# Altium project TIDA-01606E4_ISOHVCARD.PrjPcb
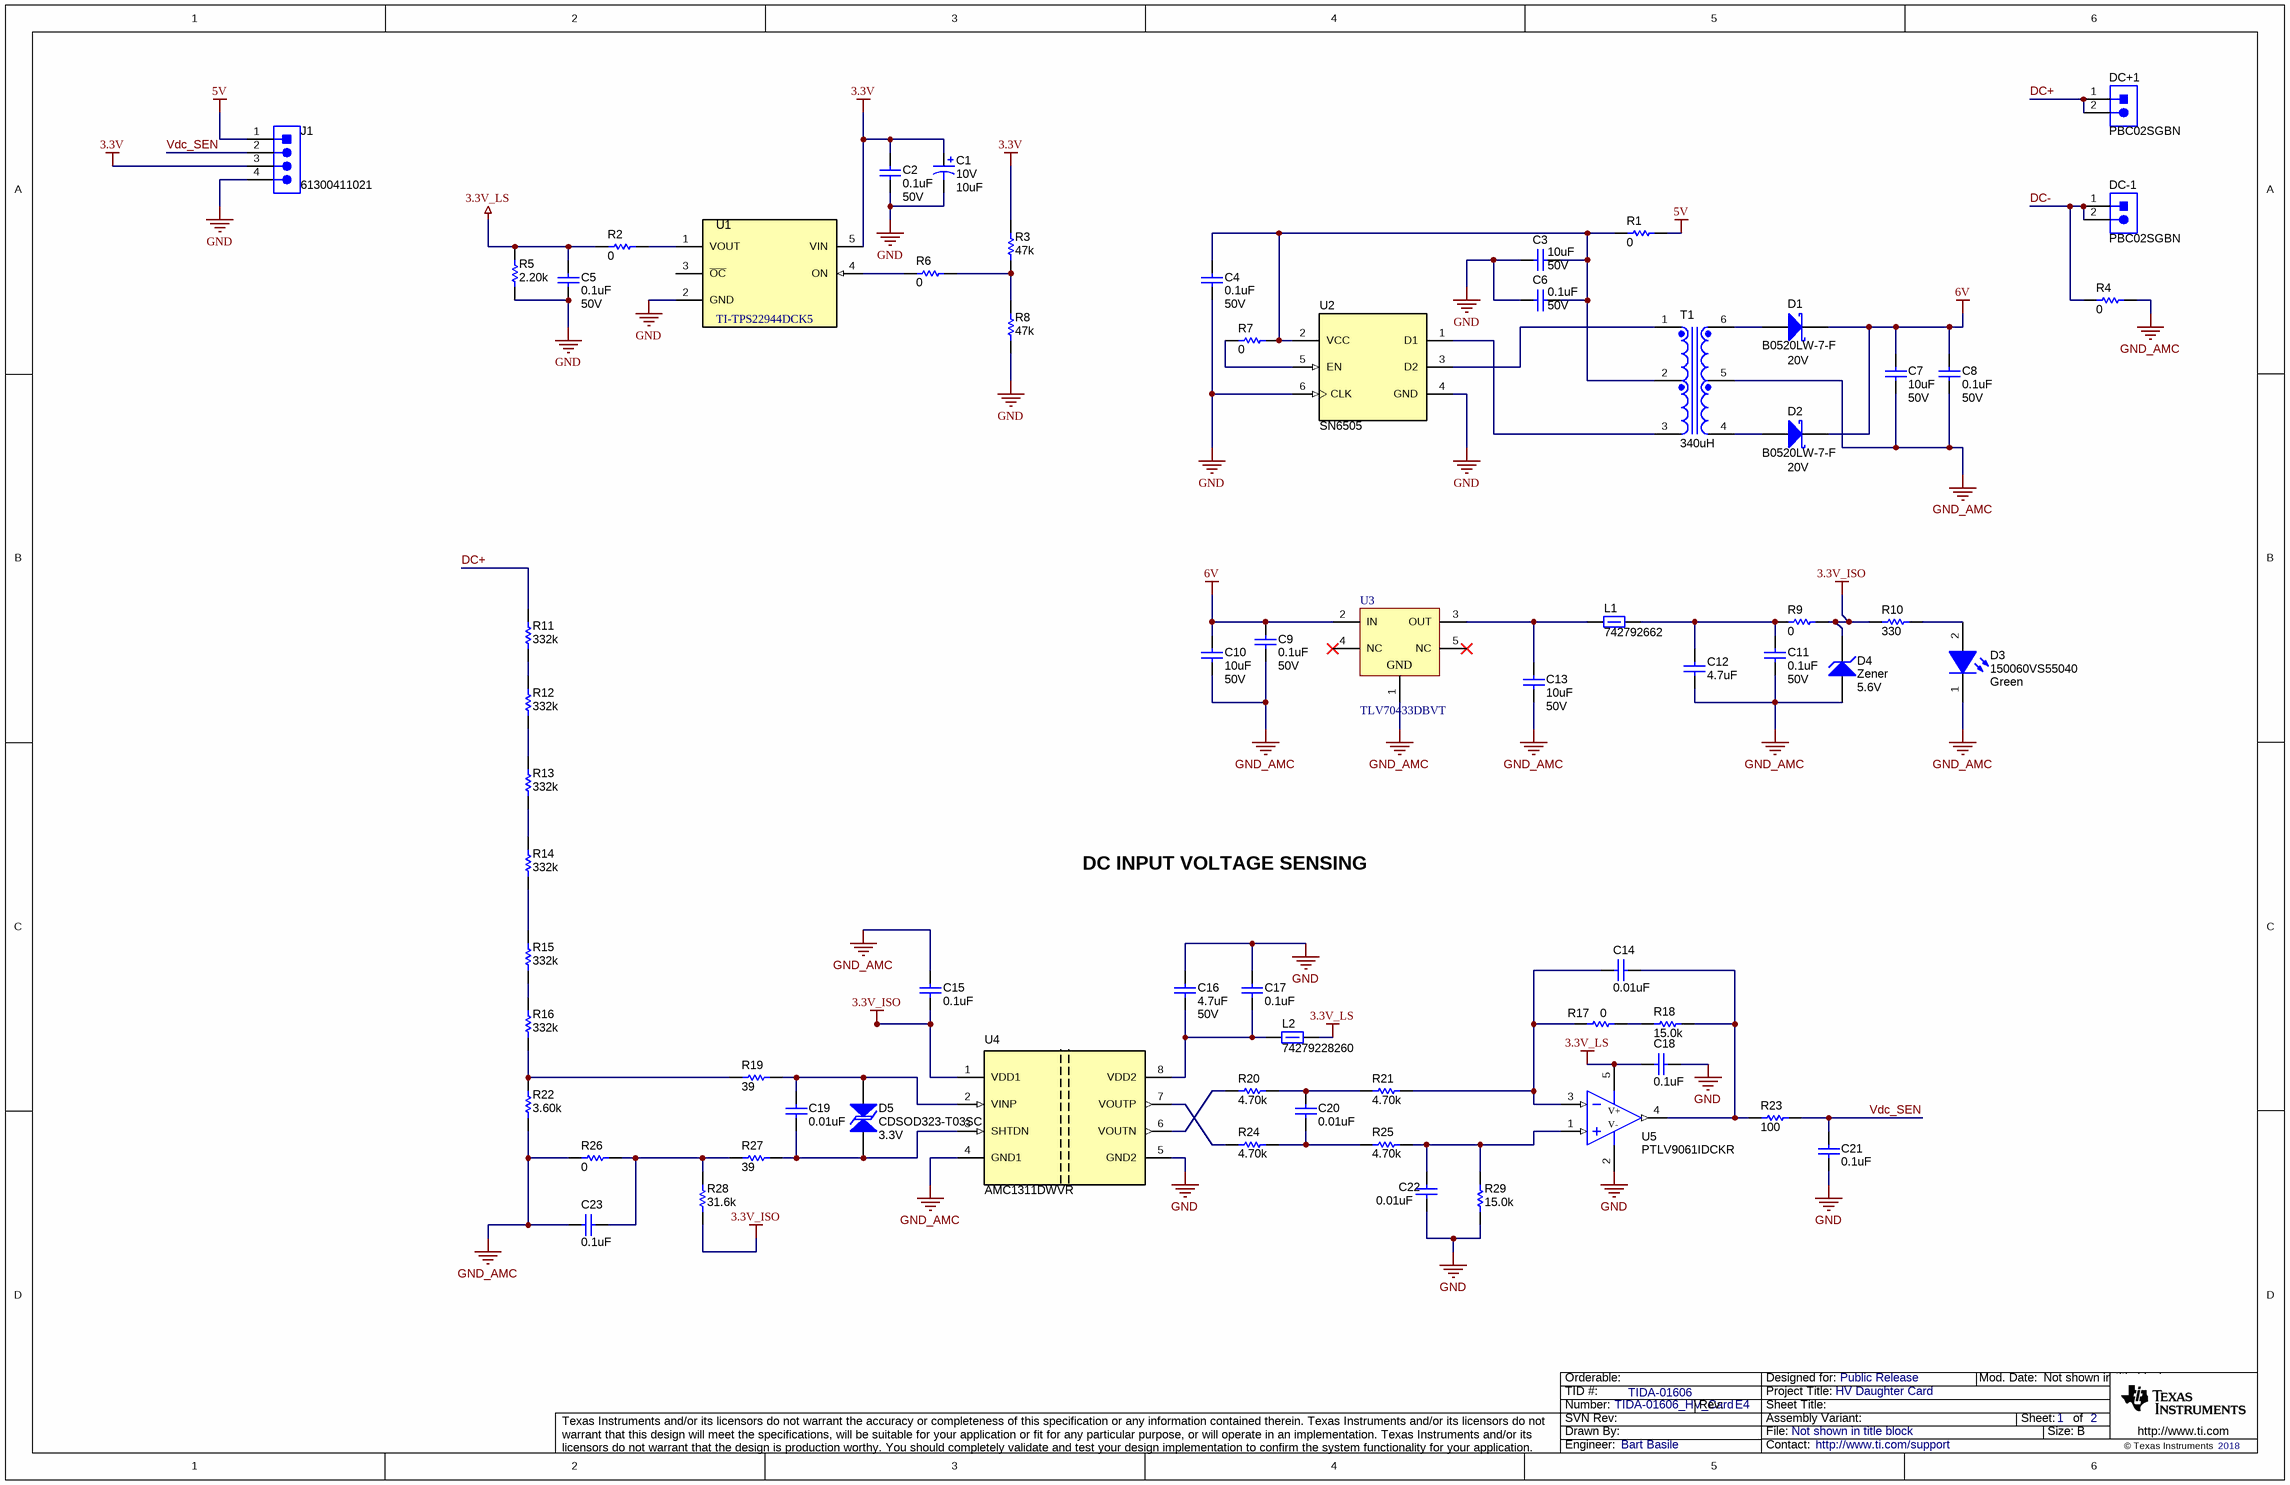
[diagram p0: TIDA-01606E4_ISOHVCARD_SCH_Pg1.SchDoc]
CopyrightYear: 2018; PCB_Layout: Bart Basile; PCB_Rev: E4; PRJ_Customer: Public Release; PRJ_Engineer: Bart Basile; PRJ_Number: TIDA-01606_HV_Card; PRJ_Title: HV Daughter Card; SCH_Rev: E4; TechSupport: http://www.ti.com/support; TID: TIDA-01606
2 sheets, 83 parts. Net scope: global (net labels, ports and power ports of the same name join across sheets).
Board file: TIDA-01606E4_ISOHVCARD_PCB.PcbDoc
Sheets:
  TIDA-01606E4_ISOHVCARD_SCH_Pg1.SchDoc
  TIDA-01606E4_ISOHVCARD_EVM_Hardware_Pg2.SchDoc

## Sheet TIDA-01606E4_ISOHVCARD_SCH_Pg1.SchDoc
size 431 x 279 mm; Date: Not shown in title block; ApprovedBy: Not shown in title block; CheckedBy: Not shown in title block; Author: Not shown in title block; CompanyName: Not shown in title block; Engineer: Not shown in title block; Organization: Not shown in title block; Address1: Not shown in title block; Address2: Not shown in title block; Address3: Not shown in title block; Address4: Not shown in title block; DocumentNumber: 1; Revision: Use project parameter SCH_Rev; SheetNumber: 1; SheetTotal: 2; PageSetup: Record=PageOptions¦CenterHorizontal=True¦CenterVertical=True¦PrintScale=1.00¦XCorrection=1.00¦YCorrection=1.00¦PrintKind=0¦BorderSize=5000000¦LeftOffset=0¦BottomOffset=0¦Orientation=2¦PaperLength=1000¦PaperWidth=1000¦Scale=100¦PaperSource=15¦PrintQuality=600¦MediaType=1¦DitherType=10¦PaperKind=Letter¦PrintScaleMode=1

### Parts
C1  VDC_V: 10V  ValueDisplayed: 10uF  [3216-18]  (hidden comment: TAJA106M010RNJ)
C2  ValueDisplayed: 0.1uF  VDC_V: 50V  [0603]  (hidden comment: 885012206095)
C3  ValueDisplayed: 10uF  VDC_V: 50V  [1210_280]  (hidden comment: C3225X7R1H106M250AC)
C4  ValueDisplayed: 0.1uF  VDC_V: 50V  [0603]  (hidden comment: 885012206095)
C5  ValueDisplayed: 0.1uF  VDC_V: 50V  [0603]  (hidden comment: 885012206095)
C6  ValueDisplayed: 0.1uF  VDC_V: 50V  [0603]  (hidden comment: 885012206095)
C7  ValueDisplayed: 10uF  VDC_V: 50V  [1210_280]  (hidden comment: C3225X7R1H106M250AC)
C8  ValueDisplayed: 0.1uF  VDC_V: 50V  [0603]  (hidden comment: 885012206095)
C9  ValueDisplayed: 0.1uF  VDC_V: 50V  [0603]  (hidden comment: 885012206095)
C10  ValueDisplayed: 10uF  VDC_V: 50V  [1210_280]  (hidden comment: C3225X7R1H106M250AC)
C11  ValueDisplayed: 0.1uF  VDC_V: 50V  [0603]  (hidden comment: 885012206095)
C12  ValueDisplayed: 4.7uF  [0805_HV]  (hidden comment: GRM21BR61H475KE51L)
C13  ValueDisplayed: 10uF  VDC_V: 50V  [1210_280]  (hidden comment: C3225X7R1H106M250AC)
C14  ValueDisplayed: 0.01uF  [0603]  (hidden comment: Capacitor)
C15  ValueDisplayed: 0.1uF  [0603]  (hidden comment: Capacitor)
C16  ValueDisplayed: 4.7uF  VDC_V: 50V  [0805_HV]  (hidden comment: GRM21BR61H475KE51L)
C17  ValueDisplayed: 0.1uF  [0603]  (hidden comment: Capacitor)
C18  ValueDisplayed: 0.1uF  [0603]  (hidden comment: Capacitor)
C19  ValueDisplayed: 0.01uF  [0603]  (hidden comment: Capacitor)
C20  ValueDisplayed: 0.01uF  [0603]  (hidden comment: Capacitor)
C21  ValueDisplayed: 0.1uF  [0603]  (hidden comment: Capacitor)
C22  ValueDisplayed: 0.01uF  [0603]  (hidden comment: Capacitor)
C23  ValueDisplayed: 0.1uF  [0603]  (hidden comment: Capacitor)
D1  B0520LW-7-F  value 20V  [SOD-123]
D2  B0520LW-7-F  value 20V  [SOD-123]
D3  150060VS55040  value Green  [WL-SMCD-0603]
D4  Zener  value 5.6V  [SOD-123]
D5  CDSOD323-T03SC  value 3.3V  [SOD-323-Bi]
DC+1  PBC02SGBN  [Sullins_PxC02SGBN]
DC-1  PBC02SGBN  [Sullins_PxC02SGBN]
J1  61300411021  [Wurth_61300411021]
L1  742792662  [0603]
L2  74279228260  [0603]
R1  ValueDisplayed: 0  [0603]  (hidden comment: ERJ-3GEY0R00V)
R2  ValueDisplayed: 0  [0603]  (hidden comment: ERJ-3GEY0R00V)
R3  ValueDisplayed: 47k  [0603]  (hidden comment: Resistor)
R4  ValueDisplayed: 0  [0603]  (hidden comment: ERJ-3GEY0R00V)
R5  ValueDisplayed: 2.20k  [0603]  (hidden comment: Resistor)
R6  ValueDisplayed: 0  [0402]  (hidden comment: CRCW04020000Z0ED)
R7  ValueDisplayed: 0  [0603]  (hidden comment: ERJ-3GEY0R00V)
R8  ValueDisplayed: 47k  [0603]  (hidden comment: Resistor)
R9  ValueDisplayed: 0  [0603]  (hidden comment: ERJ-3GEY0R00V)
R10  ValueDisplayed: 330  [0603]  (hidden comment: RC0603JR-07330RL)
R11  ValueDisplayed: 332k  [MMU_0102]  (hidden comment: MMU01020C3323FB300)
R12  ValueDisplayed: 332k  [MMU_0102]  (hidden comment: MMU01020C3323FB300)
R13  ValueDisplayed: 332k  [MMU_0102]  (hidden comment: MMU01020C3323FB300)
R14  ValueDisplayed: 332k  [MMU_0102]  (hidden comment: MMU01020C3323FB300)
R15  ValueDisplayed: 332k  [MMU_0102]  (hidden comment: MMU01020C3323FB300)
R16  ValueDisplayed: 332k  [MMU_0102]  (hidden comment: MMU01020C3323FB300)
R17  ValueDisplayed: 0  [0603]  (hidden comment: Resistor)
R18  ValueDisplayed: 15.0k  [0603]  (hidden comment: Resistor)
R19  ValueDisplayed: 39  [0603]  (hidden comment: Resistor)
R20  ValueDisplayed: 4.70k  [0603]  (hidden comment: Resistor)
R21  ValueDisplayed: 4.70k  [0603]  (hidden comment: Resistor)
R22  ValueDisplayed: 3.60k  [MMU_0102]  (hidden comment: MMU01020C3601FB300)
R23  ValueDisplayed: 100  [0603]  (hidden comment: ERJ-3EKF1000V)
R24  ValueDisplayed: 4.70k  [0603]  (hidden comment: Resistor)
R25  ValueDisplayed: 4.70k  [0603]  (hidden comment: Resistor)
R26  ValueDisplayed: 0  [0603]  (hidden comment: ERJ-3GEY0R00V)
R27  ValueDisplayed: 39  [0603]  (hidden comment: Resistor)
R28  ValueDisplayed: 31.6k  [0603]  (hidden comment: Resistor)
R29  ValueDisplayed: 15.0k  [0603]  (hidden comment: Resistor)
T1  ValueDisplayed: 340uH  [Wurth_750313638]  (hidden comment: 750313638)
U1  TI-TPS22944DCK5  [DCK0005A_N]
U2  SN6505  [DBV0006A_N]
U3  TLV70433DBVT  [DBV0005A_N]
U4  AMC1311DWVR  [DWV0008A]
U5  PTLV9061IDCKR  [DCK0005A_N]

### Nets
3.3V: C1.1(+) C2.2 J1.3 R3.2 U1.5(VIN)
3.3V_ISO: C15.2 D4.1(K) R9.2 R10.1 R28.1 U4.1(VDD1)
3.3V_LS: C5.2 C18.1 L2.2 R2.1 R5.1 U5.5(V+)
5V: J1.1 R1.2
6V: C7.1 C8.1 C9.1 C10.2 D1.1(K) D2.1(K) U3.2(IN)
GND: C1.2(-) C2.1 C3.1 C4.1 C5.1 C6.1 C16.1 C17.1 C18.2 C21.2 C22.2 J1.4 R5.2 R8.1 R29.1 U1.2(GND) U2.4(GND) U2.6(CLK) U4.5(GND2) U5.2(V-)
GND_AMC: C7.2 C8.2 C9.2 C10.1 C11.2 C12.1 C13.1 C15.1 C23.1 D3.1(K) D4.2(A) R4.2 R22.1 R26.1 T1.5 U3.1(GND) U4.4(GND1)
DC+: DC+1.1 DC+1.2 R11.2
DC-: DC-1.1 DC-1.2 R4.1
Vdc_SEN: C21.1 J1.2 R23.2
NetC3_2: C3.2 C4.2 C6.2 R1.1 R7.1 T1.2 U2.2(VCC)
NetC11_1: C11.1 C12.2 L1.2 R9.1
NetC13_2: C13.2 L1.1 U3.3(OUT)
NetC14_1: C14.1 R17.1 R21.2 U5.3(-IN)
NetC14_2: C14.2 R18.1 R23.1 U5.4(OUT)
NetC16_2: C16.2 C17.2 L2.1 U4.8(VDD2)
NetC19_1: C19.1 D5.2 R19.2 U4.2(VINP)
NetC19_2: C19.2 D5.1 R27.2 U4.3(SHTDN)
NetC20_1: C20.1 R20.2 R21.1
NetC20_2: C20.2 R24.2 R25.1
NetC22_1: C22.1 R25.2 R29.2 U5.1(+IN)
NetC23_2: C23.2 R26.2 R27.1 R28.2
NetD1_2: D1.2(A) T1.6
NetD2_2: D2.2(A) T1.4
NetD3_2: D3.2(A) R10.2
NetR2_2: R2.2 U1.1(VOUT)
NetR3_1: R3.1 R6.2 R8.2
NetR6_1: R6.1 U1.4(ON)
NetR7_2: R7.2 U2.5(EN)
NetR11_1: R11.1 R12.2
NetR12_1: R12.1 R13.2
NetR13_1: R13.1 R14.2
NetR14_1: R14.1 R15.2
NetR15_1: R15.1 R16.2
NetR16_1: R16.1 R19.1 R22.2
NetR17_2: R17.2 R18.2
NetR20_1: R20.1 U4.6(VOUTN)
NetR24_1: R24.1 U4.7(VOUTP)
NetT1_1: T1.1 U2.3(D2)
NetT1_3: T1.3 U2.1(D1)

Not connected (* = marked no-connect by the designer): U1 3(~{OC}); U3 4(NC)* 5(NC)*

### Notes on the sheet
- DC INPUT VOLTAGE SENSING

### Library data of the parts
C1 = CMP-0011478-2: CAP, TA, 10 uF, 10 V, +/- 20%, 3 ohm, SMD; Manufacturer: AVX; TaMin_C: -55°C; ESR_ohm: 3; Polarized: Y; SizeAreaWB_mm2: 10.92; Value1: 3 ohm; U/M: EA; Value: 10uF; TaMax_C: 125°C; SizeZ_mm: 1.8; SizeX_mm: 3.2; SizeY_mm: 1.6; SizeArea_mm2: 5.12; CompType: Capacitor; Cap_F: 10µF; AEC Category: Q200
C2 C4-C6 C8 C9 C11 = CMP-0006837-4: CAP, CERM, 0.1 uF, 50 V, +/- 10%, X7R, 0603; Manufacturer: Wurth Elektronik; Polarized: N; Value: 0.1uF; U/M: EA; Cap_F: 100nF; Value1: Unknown; TaMin_C: -55°C; TaMax_C: 125°C; AEC Category: Q200; SizeArea_mm2: 1.28; SizeAreaWB_mm2: 4.68; SizeX_mm: 1.6; SizeY_mm: 0.8; SizeZ_mm: 1
C3 C7 C10 C13 = CMP-0009120-1: CAP, CERM, 10 uF, 50 V, +/- 20%, X7R, 1210; Manufacturer: TDK; Polarized: N; Value: 10uF; U/M: EA; Cap_F: 10µF; Value1: Unknown; TaMin_C: -55°C; TaMax_C: 125°C; Cap_Case: 1210; AEC Category: Q200; SizeArea_mm2: 8; SizeAreaWB_mm2: 14.7; SizeX_mm: 3.2; SizeY_mm: 2.5; SizeZ_mm: 2.8
C12 = CMP-0008309-2: CAP, CERM, 4.7 uF, 50 V, +/- 10%, X5R, 0805; Manufacturer: MuRata; Polarized: N; CompType: Capacitor; Value: 4.7uF; U/M: EA; Cap_F: 4.7µF; Value1: Unknown; VDC_V: 50V; TaMin_C: -55°C; TaMax_C: 85°C; Cap_Case: 0805; AEC Category: Q200; SizeArea_mm2: 2.5; SizeAreaWB_mm2: 6.75; SizeX_mm: 2; SizeY_mm: 1.25; SizeZ_mm: 1.45
C14 C19 C20 C22 = CMP-0006828-4: CAP, CERM, 0.01 uF, 16 V, +/- 10%, X7R, 0603; PartNumber: 885012206040; Manufacturer: Wurth Elektronik; Polarized: N; Value: 0.01uF; U/M: EA; Cap_F: 10nF; Value1: Unknown; VDC_V: 16V; TaMin_C: -55°C; TaMax_C: 125°C; AEC Category: Q200; SizeArea_mm2: 1.28; SizeAreaWB_mm2: 4.68; SizeX_mm: 1.6; SizeY_mm: 0.8; SizeZ_mm: 1
C15 C17 C18 C21 C23 = CMP-0007434-4: CAP, CERM, 0.1 uF, 50 V, +/- 10%, X7R, 0603; PartNumber: GRM188R71H104KA93D; Manufacturer: MuRata; Polarized: N; Value: 0.1uF; U/M: EA; Cap_F: 100nF; Value1: Unknown; VDC_V: 50V; TaMin_C: -55°C; TaMax_C: 125°C; AEC Category: Q200; SizeArea_mm2: 1.28; SizeAreaWB_mm2: 4.68; SizeX_mm: 1.6; SizeY_mm: 0.8; SizeZ_mm: 1
C16 = CMP-0008309-2: CAP, CERM, 4.7 uF, 50 V, +/- 10%, X5R, 0805; Manufacturer: MuRata; Polarized: N; Value: 4.7uF; U/M: EA; Cap_F: 4.7µF; Value1: Unknown; TaMin_C: -55°C; TaMax_C: 85°C; Cap_Case: 0805; AEC Category: Q200; SizeArea_mm2: 2.5; SizeAreaWB_mm2: 6.75; SizeX_mm: 2; SizeY_mm: 1.25; SizeZ_mm: 1.45
D1 D2 = CMP-0080707-1: Diode, Schottky, 20 V, 0.5 A, SOD-123; Manufacturer: Diodes Inc.; Vf_V: 3.3dV; Value1: 0.5A; Value2: 0.33V; Io_A: 5dA; TJmax_C: 125°C; AEC Category: Q101; AEC Qualified: N; SizeArea_mm2: 6.545; SizeAreaWB_mm2: 13.095; SizeX_mm: 3.85; SizeY_mm: 1.7; SizeZ_mm: 1.35
D3 = CMP-0081648-1: LED, Green, SMD; Manufacturer: Wurth Elektronik; Io_A: 20mA; Power_TotalModule: 48mW; Vr_V: 5V; SizeAreaWB_mm2: 4.68; Tjmax_C: 115°C; Value1: 0.048W; Angle: 140; SizeZ_mm: 0.5; SizeX_mm: 1.6; SizeY_mm: 0.8; Ir_A: 10µA; Vf_V: 2V; SizeArea_mm2: 1.28; Type: AlInGaP
D4 = CMP-0005803-1: Diode, Zener, 5.6 V, 500 mW, SOD-123; PartNumber: MMSZ5232B-7-F; Manufacturer: Diodes Inc.; U/M: EA; Power_W: 500mW; Value1: 0.5W; RJA_CperW: 350; AEC Category: Q101; SizeArea_mm2: 6.545; SizeAreaWB_mm2: 13.095; SizeX_mm: 3.85; SizeY_mm: 1.7; SizeZ_mm: 1.35
D5 = CMP-0006063-1: Diode, TVS, Bi, 3.3 V, 10.9 Vc, SOD323, 2-Leads, Body 1.9x1.45mm, No Polarity Mark; Manufacturer: Bourns; Value1: W; U/M: EA; AEC Qualified: N; AEC Category: Q101
DC+1 DC-1 = CMP-0054714-1: Header, 2.54 mm, 2x1, Gold, R/A, TH; Manufacturer: Sullins Connector Solutions; CNHeader: FALSE; Current_A: 3A; Shrouded: N; Gender: Male; Voltage_V: 1.8kV; Row_Count: 1; Pitch_mm: 2.54; Cert_UL: Y
J1 = CMP-0054797-1: Header, 2.54 mm, 4x1, Gold, R/A, TH; Manufacturer: Wurth Elektronik; CNHeader: TRUE; Shrouded: N; Gender: Male; Row_Count: 1; Pitch_mm: 2.54; CT: FALSE
L1 = CMP-0003201-2: Ferrite Bead, 1000 ohm @ 100 MHz, 0.6 A, 0603; Manufacturer: Wurth Elektronik; Ztyp@1GHz_Ohm: 185.971; ZTyp@100MHz_Ohm: 1k; SizeAreaWB_mm2: 4.68; DCR_ohm: 3d; Value1: 0.3 ohm; Imax_A: 6dA; SizeZ_mm: 1; SizeX_mm: 1.6; SizeY_mm: 0.8; Value2: 0.6A; SizeArea_mm2: 1.28
L2 = CMP-0003155-2: Ferrite Bead, 26 ohm @ 100 MHz, 6.5 A, 0603; Manufacturer: Wurth Elektronik; Ztyp@1GHz_Ohm: 35.506; ZTyp@100MHz_Ohm: 26; SizeAreaWB_mm2: 4.68; DCR_ohm: 5m; Value1: 0.005 ohm; Value: 26 ohm; Imax_A: 6.5A; SizeZ_mm: 1; SizeX_mm: 1.6; SizeY_mm: 0.8; SizeArea_mm2: 1.28
R1 R2 R4 R7 R9 R26 = CMP-0025874-4: RES, 0, 5%, 0.1 W, AEC-Q200 Grade 0, 0603; Manufacturer: Panasonic; Value: 0; Value_Code: 0000; Power_W: 100mW; Value2: 0.1W; VDC_V: 50V; TempCo: 600 ppm/C; EIA_Code: E24; AEC Category: Q200; AEC Qualified: Y; SizeArea_mm2: 1.28; SizeX_mm: 1.6; SizeY_mm: 0.8; SizeZ_mm: 1; SizeAreaWB_mm2: 4.68
R3 R8 = CMP-0025925-5: RES, 47 k, 5%, 0.1 W, 0603; PartNumber: RC0603JR-0747KL; Manufacturer: Yageo; Value: 47k; Value_Code: 47k0; Power_W: 100mW; Value2: 0.1W; VDC_V: 75V; TempCo: 100 ppm/C; EIA_Code: E24; AEC Category: Q200; AEC Qualified: N; SizeArea_mm2: 1.28; SizeAreaWB_mm2: 4.68; SizeX_mm: 1.6; SizeY_mm: 0.8; SizeZ_mm: 1
R5 = CMP-0022986-5: RES, 2.20 k, 1%, 0.1 W, 0603; PartNumber: RC0603FR-072K2L; Manufacturer: Yageo; Value: 2.20k; Res_ohm: 2.2k; Value_Code: 2k20; Power_W: 100mW; Value2: 0.1W; VDC_V: 75V; TempCo: 100 ppm/C; AEC Category: Q200; AEC Qualified: N; SizeArea_mm2: 1.28; SizeAreaWB_mm2: 4.68; SizeX_mm: 1.6; SizeY_mm: 0.8; SizeZ_mm: 1
R6 = CMP-0026822-3: RES, 0, 5%, 0.063 W, AEC-Q200 Grade 0, 0402; Manufacturer: Vishay-Dale; Value: 0; Value_Code: 0000; Power_W: 63mW; Value2: 0.063W; VDC_V: 50V; TempCo: 200 ppm/C; EIA_Code: E24; AEC Category: Q200; AEC Qualified: Y; SizeArea_mm2: 0.5; SizeX_mm: 1; SizeZ_mm: 0.6
R10 = CMP-0025912-5: RES, 330, 5%, 0.1 W, 0603; Manufacturer: Yageo; Power_W: 100mW; TempCo: 100 ppm/C; Value_Code: 330R; Value: 330; EIA_Code: E24; SizeX_mm: 1.6; SizeY_mm: 0.8; SizeZ_mm: 1; Value2: 0.1W; SizeArea_mm2: 1.28; AEC Qualified: N; VDC_V: 75V; AEC Category: Q200; SizeAreaWB_mm2: 4.68
R11 = CMP-0083757-2: RES, 332 k, 1%, 0.2 W, AEC-Q200 Grade 0, 2.2x1.1mm; Manufacturer: Vishay-Semiconductor; SizeAreaWB_mm2: 6.72; SizeArea_mm2: 2.42; AEC Qualified: Y; AEC Category: Q200; Value: 332k; SizeZ_mm: 1.1; EIA_Code: E96; TempCo: 50 ppm/C; AEC Grade: 0; Power_W: 200mW; Value2: 0.2W; CompType: Resistor; SizeX_mm: 2.2
R12-R16 = CMP-0083757-2: RES, 332 k, 1%, 0.2 W, AEC-Q200 Grade 0, 2.2x1.1mm; Manufacturer: Vishay-Semiconductor; SizeAreaWB_mm2: 6.72; SizeArea_mm2: 2.42; AEC Qualified: Y; AEC Category: Q200; Value: 332k; SizeZ_mm: 1.1; EIA_Code: E96; TempCo: 50 ppm/C; AEC Grade: 0; Power_W: 200mW; Value2: 0.2W; SizeX_mm: 2.2
R17 = CMP-0025874-4: RES, 0, 5%, 0.1 W, AEC-Q200 Grade 0, 0603; PartNumber: ERJ-3GEY0R00V; Manufacturer: Panasonic; Value: 0; Value_Code: 0000; Power_W: 100mW; Value2: 0.1W; VDC_V: 50V; TempCo: 600 ppm/C; EIA_Code: E24; AEC Category: Q200; AEC Qualified: Y; SizeArea_mm2: 1.28; SizeX_mm: 1.6; SizeY_mm: 0.8; SizeZ_mm: 1; SizeAreaWB_mm2: 4.68
R18 R29 = CMP-0022816-5: RES, 15.0 k, 1%, 0.1 W, 0603; PartNumber: RC0603FR-0715KL; Manufacturer: Yageo; Value: 15.0k; Res_ohm: 15k; Value_Code: 15k0; Power_W: 100mW; Value2: 0.1W; VDC_V: 75V; TempCo: 100 ppm/C; EIA_Code: E96; AEC Category: Q200; AEC Qualified: N; SizeArea_mm2: 1.28; SizeX_mm: 1.6; SizeY_mm: 0.8; SizeZ_mm: 1; SizeAreaWB_mm2: 4.68
R19 R27 = CMP-0025795-4: RES, 39, 5%, 0.1 W, AEC-Q200 Grade 0, 0603; PartNumber: CRCW060339R0JNEA; Manufacturer: Vishay-Dale; Value: 39; Value_Code: 39R0; Power_W: 100mW; Value2: 0.1W; VDC_V: 75V; TempCo: 200 ppm/C; EIA_Code: E24; AEC Category: Q200; AEC Qualified: Y; AEC Grade: 0; SizeArea_mm2: 1.28; SizeX_mm: 1.6; SizeY_mm: 0.8; SizeZ_mm: 1
R20 R21 R24 R25 = CMP-0023153-5: RES, 4.70 k, 1%, 0.1 W, 0603; PartNumber: RC0603FR-074K7L; Manufacturer: Yageo; Value: 4.70k; Res_ohm: 4.7k; Value_Code: 4k70; Power_W: 100mW; Value2: 0.1W; VDC_V: 75V; TempCo: 100 ppm/C; AEC Category: Q200; AEC Qualified: N; SizeArea_mm2: 1.28; SizeAreaWB_mm2: 4.68; SizeX_mm: 1.6; SizeY_mm: 0.8; SizeZ_mm: 1
R22 = CMP-0083758-2: RES, 3.60 k, 1%, 0.3 W, AEC-Q200 Grade 0, 2.2x1.1mm; Manufacturer: Vishay-Semiconductor; Value_Code: 3k60; SizeAreaWB_mm2: 6.72; SizeArea_mm2: 2.42; AEC Qualified: Y; AEC Category: Q200; Res_ohm: 3.6k; Value: 3.60k; SizeZ_mm: 1.1; TempCo: 50 ppm/C; AEC Grade: 0; Power_W: 300mW; Value2: 0.3W; SizeX_mm: 2.2
R23 = CMP-0022679-3: RES, 100, 1%, 0.1 W, AEC-Q200 Grade 0, 0603; Manufacturer: Panasonic; Value: 100; Value_Code: 100R; Power_W: 100mW; Value2: 0.1W; TempCo: 100 ppm/C; EIA_Code: E96; AEC Category: Q200; AEC Qualified: Y; AEC Grade: 0; SizeArea_mm2: 1.28; SizeX_mm: 1.6; SizeY_mm: 0.8; SizeZ_mm: 1; U/M: EA
R28 = CMP-0022330-4: RES, 31.6 k, 1%, 0.1 W, AEC-Q200 Grade 0, 0603; PartNumber: CRCW060331K6FKEA; Manufacturer: Vishay-Dale; Value: 31.6k; Value_Code: 31k6; Power_W: 100mW; Value2: 0.1W; VDC_V: 75V; TempCo: 100 ppm/C; EIA_Code: E96; AEC Category: Q200; AEC Qualified: Y; AEC Grade: 0; SizeArea_mm2: 1.28; SizeX_mm: 1.6; SizeY_mm: 0.8; SizeZ_mm: 1
T1 = CMP-0030601-1: Transformer, 340 uH, SMT; Manufacturer: Wurth Elektronik; Value: 340uH; Lp: 340; DCR_ohm: 3.3d; Ind_H: 340µH
U1 = CMP-0034371-2: Low-Input Voltage 100 mA Current Limited Load Switch, 400 mOhms rDS(On), -40 to 85 degC, 5-pin SC70 (DCK), Green (RoHS & no Sb/Br); PartNumber: TPS22944DCKR; Manufacturer: Texas Instruments; SizeArea_mm2: 4.2; SizeAreaWB_mm2: 9.3; SizeX_mm: 2.1; SizeY_mm: 2.0; SizeZ_mm: 1.1; CompType: IC; Adjustable Current Limit(Min)(A): 0.1; AEC Category: Q200; AEC Qualified: N; Enable/Shutdown: Active High; Iq(Typ)(uA): 40; Number of FETs: 1; rDS(on) per FET(Typ)(mOhms): 400; SubFamily: Current Limited Switch; Vin(Max)(V): 5.5; Vin(Min)(V): 1.62
U2 = CMP-0076095-1: Low-Noise 1 A, 420 kHz Transformer Driver, DBV0006A (SOT-23-6); PartNumber: SN6505BDBVR; Alternate PartNumber: SN6505BDBVT; Manufacturer: Texas Instruments; CompType: IC; U/M: EA; Green_Lifecycle: Active; Green_REACh: Passed; SizeArea_mm2: 8.12; SizeAreaWB_mm2: 14.82; SizeX_mm: 2.8; SizeY_mm: 2.9; SizeZ_mm: 1.45
U3 = CMP-0035592-1: Single Output LDO, 150 mA, Fixed 3.3 V Output, 2.5 to 24 V Input, with Ultra-Low IQ, 5-pin SOT-23 (DBV), -40 to 125 degC, Green (RoHS & no Sb/Br); Manufacturer: Texas Instruments; Accuracy(%): 2; Fixed Output Options(V): 3.3; Iout(Max)(A): 0.15; Iq(Typ)(mA): 0.003; SubFamily: Single Channel LDO; Vdo(Typ)(mV): 400; Vin(Max)(V): 24; Vin(Min)(V): 2.5
U4 = CMP-0013503-2: Precision, 2-V Input, Reinforced Isolated Amplifier, DWV0008A (SOIC-8); Manufacturer: Texas Instruments; SizeX_mm: 11.5; SizeY_mm: 5.85; CompType: IC; SizeZ_mm: 2.8; SizeArea_mm2: 67.275; SizeAreaWB_mm2: 105.975; U/M: EA
U5 = CMP-0084061-1: World's Smallest Amp 10MHz, RRIO, 1.8V-5.5V op-amp delivers high performance for challenging systems, DCK0005A (SOT-SC70-5); Manufacturer: Texas Instruments; Rating: Catalog; SizeAreaWB_mm2: 9.3; SizeArea_mm2: 4.2; AEC Qualified: N; AEC Category: Q200; SizeZ_mm: 1.1; SizeY_mm: 2; CompType: IC; SizeX_mm: 2.1

## Sheet TIDA-01606E4_ISOHVCARD_EVM_Hardware_Pg2.SchDoc
size 431 x 279 mm; Date: Not shown in title block; ApprovedBy: Not shown in title block; CheckedBy: Not shown in title block; Author: Not shown in title block; CompanyName: Not shown in title block; Engineer: Not shown in title block; Organization: Not shown in title block; Address1: Not shown in title block; Address2: Not shown in title block; Address3: Not shown in title block; Address4: Not shown in title block; DocumentNumber: 1; Revision: Use project parameter SCH_Rev; SheetNumber: 2; SheetTotal: 2; PageSetup: Record=PageOptions¦CenterHorizontal=True¦CenterVertical=True¦PrintScale=1.00¦XCorrection=1.00¦YCorrection=1.00¦PrintKind=0¦BorderSize=5000000¦LeftOffset=0¦BottomOffset=0¦Orientation=2¦PaperLength=1000¦PaperWidth=1000¦Scale=100¦PaperSource=15¦PrintQuality=600¦MediaType=1¦DitherType=10¦PaperKind=Letter¦PrintScaleMode=1
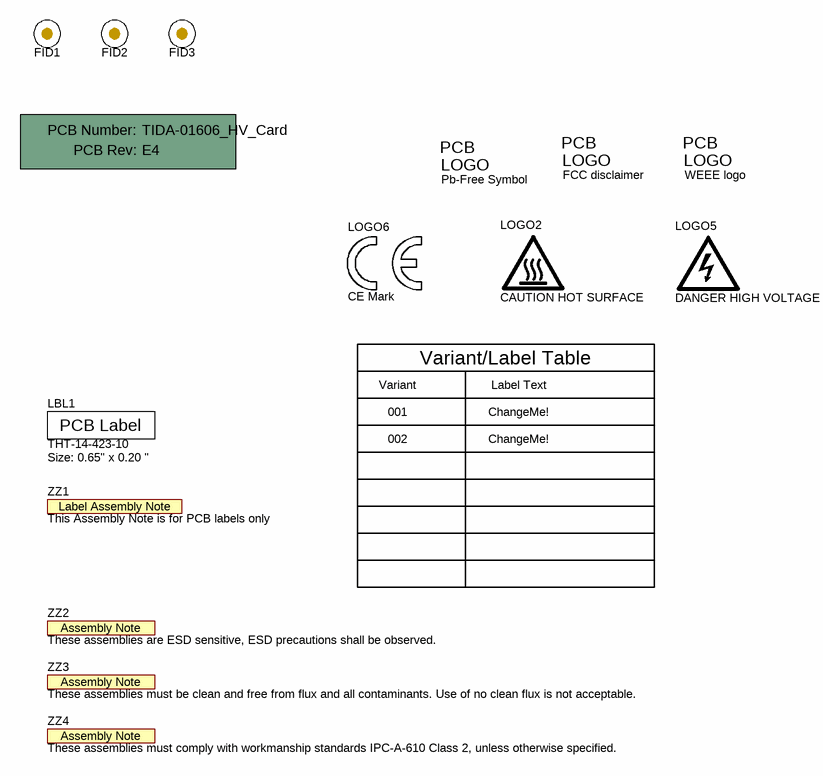
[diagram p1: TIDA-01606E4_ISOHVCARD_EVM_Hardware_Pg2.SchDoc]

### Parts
!PCB1  Printed Circuit Board  (value not drawn)  (mechanical)
FID1  Fiducial  [Fiducial10-20]  (value not drawn)
FID2  Fiducial  [Fiducial10-20]  (value not drawn)
FID3  Fiducial  [Fiducial10-20]  (value not drawn)
LBL1  THT-14-423-10  Note: Size: 0.65" x 0.20 "  [Label_650x200]
Logo1  Pb-Free Symbol  [Pb-Free_Overlay_Small]  (no BOM)
LOGO2  CAUTION HOT SURFACE  [IEC_HotSurface_Small]  (no BOM)
Logo3  FCC disclaimer  [FCC_disclaimer]  (no BOM)
Logo4  WEEE logo  [WEEE_Minimum]  (no BOM)
LOGO5  DANGER HIGH VOLTAGE  [IEC_HighVoltage_Small]  (no BOM)
LOGO6  CE Mark  [CE_Mark_5mm]  (no BOM)
ZZ1  This Assembly Note is for PCB labels only  [AssemblyNoteLabel]  (no BOM)
ZZ2  These assemblies are ESD sensitive, ESD precautions shall be observed.  [AssemblyNote]  (no BOM)
ZZ3  These assemblies must be clean and free from flux and all contaminants. Use of no clean flux is not acceptable.  [AssemblyNote]  (no BOM)
ZZ4  These assemblies must comply with workmanship standards IPC-A-610 Class 2, unless otherwise specified.  [AssemblyNote]  (no BOM)

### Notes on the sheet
- Variant
- Variant/Label Table
- Label Text
- 001
- 002
- ChangeMe!

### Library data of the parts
!PCB1 = CMP-0003618-2: Manufacturer: Any; PartNumber: TIDA-01606_HV_Card
FID1-FID3 = CMP-0077181-1: Fiducial mark.  There is nothing to buy or mount.
LBL1 = CMP-0003625-1: Thermal Transfer Printable Labels, 0.650" W x 0.200" H - 10,000 per roll; Manufacturer: Brady; CompType: Label
Logo1 = CMP-0074839-1: SymbolCreator: a0412235
LOGO2 = CMP-0074837-1: IEC 61010-1 Hot Surface Warning; SymbolCreator: a0412235
Logo3 = CMP-0074847-1: FCC_disclaimer; Library Reference: Logo
Logo4 = CMP-0074769-1
LOGO5 = CMP-0074835-1: IEC 61010-1 High Voltage Warning; SymbolCreator: a0412235
LOGO6 = CMP-0074844-1: SymbolCreator: a0412235
ZZ1 = CMP-0003616-3
ZZ2 = CMP-0077236-1
ZZ3 = CMP-0077237-1
ZZ4 = CMP-0077238-1

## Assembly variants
001: not fitted C23 FID1 FID2 FID3 R8 R28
